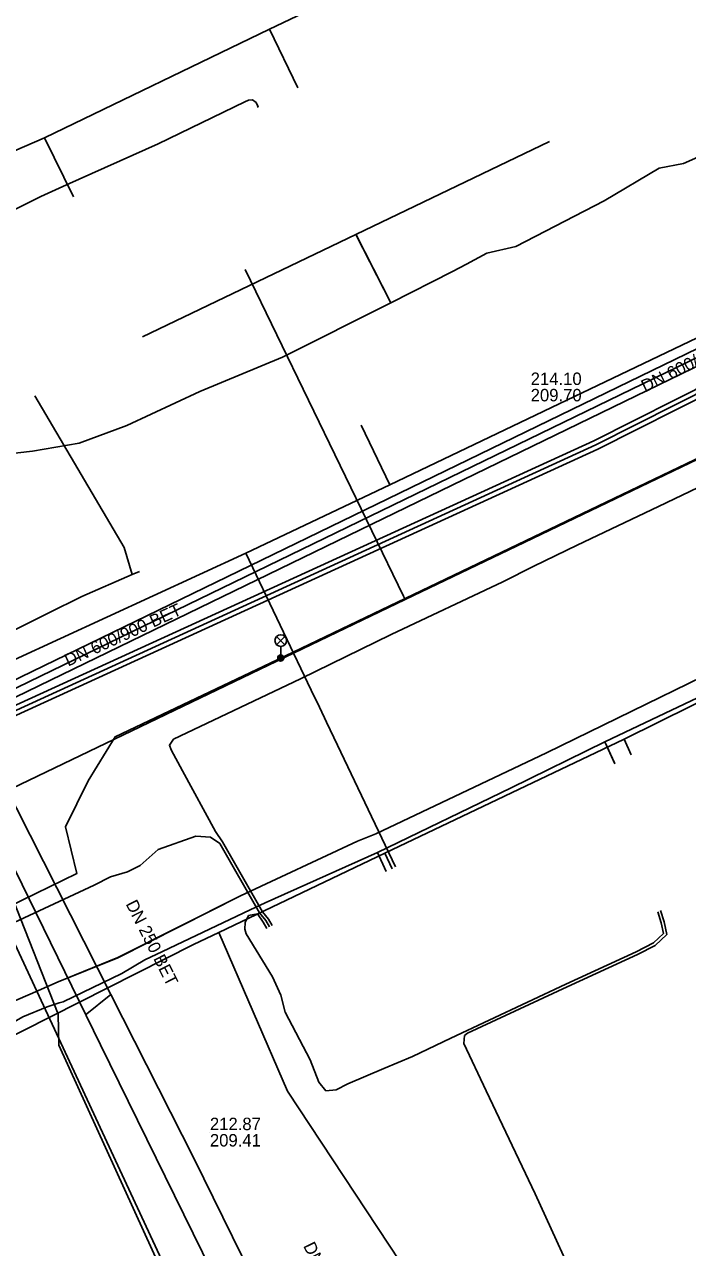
# Model space of a CAD drawing. Extents: x -595540 to -593988, y -1160850 to -1159202.
# Drawn here: x -595447.6 to -595405, y -1159984.1 to -1159905.6 of the extents above; entities that cross this region are included whole.
import ezdxf

# ---------------------------------------------------------------- set-up
doc = ezdxf.new("R2010")
doc.units = 0
for name, color, linetype in [('BVK-JEDNOTNA_popisy', 7, 'Continuous'), ('BVK-JEDNOTNA_trasa sítě', 7, 'Continuous'), ('BVK-JEDNOTNA_trasa sítě obvodem', 7, 'Continuous'), ('BVK-VODOVOD_trasa sítě', 7, 'Continuous'), ('CETIN_kabel podzemní', 7, 'Continuous'), ('CETIN_kabelovod', 7, 'Continuous'), ('DESTOVA_trasa neprovozované sítě', 7, 'Continuous'), ('DSP-SDEL-VODAFONE_kabel', 7, 'Continuous'), ('EON-NN_kabel', 7, 'Continuous'), ('EON-NN_kabel zrušené sítě', 7, 'Continuous'), ('EON-SDEL_kabel', 7, 'Continuous'), ('INNOGY-NTL_trasa sítě', 7, 'Continuous'), ('INNOGY-STL_trasa sítě', 7, 'Continuous'), ('QUANTCOM_kabel', 7, 'Continuous'), ('TSB_kabel VO', 7, 'Continuous'), ('TSB_lampy VO', 7, 'Continuous')]:
    doc.layers.add(name, color=color, linetype=linetype)

msp = doc.modelspace()

# ---------------------------------------------------------------- linework, layer by layer
at = {"layer": 'BVK-JEDNOTNA_popisy'}
for p, q in [((-595415.078, -1159928.872), (-595415.078, -1159928.872)), ((-595435.658, -1159976.709), (-595435.658, -1159976.709))]:
    msp.add_line(p, q, dxfattribs=at)
at = {"layer": 'BVK-JEDNOTNA_trasa sítě'}
for p, q in [((-595373.317, -1159913.594), (-595410.896, -1159932.598)), ((-595410.896, -1159932.598), (-595450.666, -1159950.799)), ((-595423.214, -1160005.707), (-595436.668, -1159978.426))]:
    msp.add_line(p, q, dxfattribs=at)
msp.add_lwpolyline([(-595436.668, -1159978.426), (-595442.021, -1159967.873), (-595450.666, -1159950.799)], dxfattribs=at)
at = {"layer": 'BVK-JEDNOTNA_trasa sítě obvodem'}
for p, q in [((-595411.031, -1159932.33), (-595373.452, -1159913.326)), ((-595373.182, -1159913.862), (-595410.761, -1159932.866)), ((-595450.791, -1159950.526), (-595411.021, -1159932.325)), ((-595410.771, -1159932.871), (-595450.541, -1159951.072))]:
    msp.add_line(p, q, dxfattribs=at)
at = {"layer": 'BVK-VODOVOD_trasa sítě'}
for points in [[(-595374.704, -1159919.267), (-595375.214, -1159919.512), (-595415.987, -1159939.088), (-595423.124, -1159942.515), (-595450.033, -1159955.434)], [(-595423.124, -1159942.515), (-595423.229, -1159942.297), (-595433.388, -1159921.334)], [(-595449.912, -1159956.327), (-595449.568, -1159957.045), (-595442.672, -1159971.097), (-595426.629, -1160003.791), (-595426.262, -1160004.538)]]:
    msp.add_lwpolyline(points, dxfattribs=at)
at = {"layer": 'CETIN_kabel podzemní'}
for points in [[(-595539.58, -1159992.625), (-595456.78, -1159952.4), (-595371.39, -1159910.95), (-595397.99, -1159856.09)], [(-595431.84, -1159905.91), (-595417.26, -1159898.95)], [(-595384.48, -1159904.94), (-595387.33, -1159906.22), (-595389.03, -1159907.36), (-595390.14, -1159908.48), (-595391.65, -1159910.23), (-595392.29, -1159910.87), (-595393.89, -1159911.68), (-595399.16, -1159914.34), (-595401.97, -1159915.72), (-595402.43, -1159915.85), (-595402.7, -1159915.68), (-595403.68, -1159914.15), (-595403.97, -1159913.96), (-595405.27, -1159914.52), (-595406.83, -1159914.82), (-595410.37, -1159916.92), (-595416.03, -1159919.85), (-595417.89, -1159920.28), (-595419.19, -1159921), (-595420.09, -1159921.45), (-595424.06, -1159923.47)], [(-595446.26, -1159912.89), (-595431.84, -1159905.91)], [(-595431.84, -1159905.91), (-595430.01, -1159909.68)], [(-595459.45, -1159910.18), (-595456.1, -1159917.14), (-595446.26, -1159912.89)], [(-595446.26, -1159912.89), (-595444.4, -1159916.66)], [(-595426.29, -1159919.08), (-595413.88, -1159913.12)], [(-595426.29, -1159919.08), (-595439.99, -1159925.66)], [(-595424.06, -1159923.47), (-595426.29, -1159919.08)], [(-595424.06, -1159923.47), (-595431.01, -1159926.97), (-595436.31, -1159929.17), (-595440.98, -1159931.34), (-595444.04, -1159932.48), (-595447.05, -1159933), (-595449.89, -1159933.31), (-595450.61, -1159933.59)], [(-595410.33, -1159951.65), (-595401.35, -1159947.39), (-595395.93, -1159944.76)], [(-595409.09, -1159951.49), (-595395.99, -1159944.99)], [(-595424.44, -1159958.81), (-595409.09, -1159951.49)], [(-595409.09, -1159951.49), (-595408.62, -1159952.49)], [(-595424.91, -1159958.75), (-595416.33, -1159954.6), (-595410.33, -1159951.65)], [(-595410.33, -1159951.65), (-595409.69, -1159953)], [(-595438.7, -1159965.12), (-595433.07, -1159962.44), (-595432.12, -1159962), (-595424.91, -1159958.75)], [(-595435.09, -1159963.89), (-595424.44, -1159958.81)], [(-595424.91, -1159958.75), (-595424.34, -1159959.98)], [(-595424.44, -1159958.81), (-595423.97, -1159959.8)], [(-595436.71, -1159964.66), (-595435.09, -1159963.89)], [(-595435.09, -1159963.89), (-595430.67, -1159974.08), (-595417.68, -1159993.79), (-595411.71, -1159990.96), (-595410.95, -1159992.57), (-595409.27, -1159996.12), (-595406.792, -1159999.807)], [(-595459.75, -1159976.14), (-595453.17, -1159972.99), (-595436.71, -1159964.66)], [(-595460.4, -1159976.08), (-595453.22, -1159972.52), (-595447.65, -1159969.31), (-595446.09, -1159968.67), (-595445.33, -1159968.41), (-595445.08, -1159968.35), (-595441.31, -1159966.53), (-595439.83, -1159965.66), (-595438.7, -1159965.12)]]:
    msp.add_lwpolyline(points, dxfattribs=at)
at = {"layer": 'CETIN_kabelovod'}
for points in [[(-595373.4, -1159911.37), (-595455.19, -1159951.08)], [(-595372.97, -1159912.27), (-595454.76, -1159951.99)]]:
    msp.add_lwpolyline(points, dxfattribs=at)
at = {"layer": 'DESTOVA_trasa neprovozované sítě'}
msp.add_line((-595443.66, -1159969.2), (-595442.021, -1159967.873), dxfattribs=at)
at = {"layer": 'DSP-SDEL-VODAFONE_kabel'}
for points in [[(-595467.4, -1159905.06), (-595466.64, -1159906.67), (-595466.23, -1159907.64), (-595463.85, -1159912.58), (-595463.25, -1159913.8), (-595459.54, -1159921.22), (-595456.44, -1159927.74), (-595456.16, -1159928.54), (-595455.24, -1159930.24), (-595453.23, -1159934.47), (-595452.7, -1159934.26), (-595451.82, -1159933.98), (-595451.15, -1159933.8), (-595450.608, -1159933.589), (-595449.89, -1159933.31), (-595447.05, -1159933), (-595444.04, -1159932.48), (-595440.98, -1159931.34), (-595436.31, -1159929.17), (-595431.01, -1159926.97), (-595424.06, -1159923.47)], [(-595424.06, -1159923.47), (-595420.09, -1159921.45), (-595419.19, -1159921), (-595417.89, -1159920.28), (-595416.03, -1159919.85), (-595410.37, -1159916.92), (-595406.83, -1159914.82), (-595405.27, -1159914.52), (-595403.97, -1159913.96), (-595403.68, -1159914.15), (-595402.7, -1159915.68), (-595402.43, -1159915.85), (-595401.97, -1159915.72), (-595399.16, -1159914.34), (-595393.89, -1159911.68)], [(-595424.06, -1159923.47), (-595426.273, -1159919.113)], [(-595382.9, -1159931.31), (-595383.54, -1159931.62), (-595392.92, -1159936.14), (-595393.26, -1159936.82), (-595393.43, -1159937.76), (-595393.63, -1159942.73), (-595393.7, -1159943.32), (-595394.06, -1159943.69), (-595394.93, -1159944.27), (-595395.93, -1159944.76), (-595401.35, -1159947.39), (-595410.33, -1159951.65)], [(-595410.33, -1159951.65), (-595416.33, -1159954.6), (-595424.91, -1159958.75), (-595432.12, -1159962), (-595433.07, -1159962.44), (-595438.696, -1159965.12), (-595439.83, -1159965.66), (-595441.31, -1159966.53), (-595445.08, -1159968.35), (-595445.33, -1159968.41), (-595446.09, -1159968.67), (-595447.65, -1159969.31), (-595453.22, -1159972.52), (-595460.4, -1159976.08), (-595467.41, -1159979.05), (-595468.6, -1159979.68), (-595470.64, -1159980.67), (-595474.74, -1159982.73)], [(-595410.33, -1159951.65), (-595409.668, -1159953.058)]]:
    msp.add_lwpolyline(points, dxfattribs=at)
at = {"layer": 'EON-NN_kabel'}
for points in [[(-595431.666, -1159963.441), (-595431.9, -1159963.031), (-595432.282, -1159962.567), (-595434.853, -1159958.08), (-595435.3, -1159957.41), (-595437.42, -1159953.51), (-595438.15, -1159952.16), (-595438.26, -1159951.86), (-595437.99, -1159951.48), (-595429.84, -1159947.6), (-595424.03, -1159944.77), (-595416.86, -1159941.38), (-595414.87, -1159940.37), (-595412.09, -1159939.04), (-595406.88, -1159936.55), (-595401.29, -1159933.87)], [(-595431.84, -1159963.54), (-595432.074, -1159963.13), (-595432.471, -1159962.639), (-595435.027, -1159958.18), (-595435.61, -1159957.78), (-595436.56, -1159957.71), (-595438.98, -1159958.57), (-595440.14, -1159959.6), (-595440.95, -1159960), (-595442.04, -1159960.33), (-595443.09, -1159960.86), (-595453.64, -1159965.78), (-595455.63, -1159966.8), (-595457.79, -1159967.74), (-595462.39, -1159969.77), (-595463.93, -1159970.92), (-595469.24, -1159973.4), (-595479.08, -1159978.13), (-595479.43, -1159978.899), (-595478.027, -1159980.281), (-595476.001, -1159984.615)], [(-595406.926, -1159962.569), (-595406.712, -1159963.271), (-595406.556, -1159963.953), (-595407.203, -1159964.562), (-595408.313, -1159965.127), (-595412.828, -1159967.204), (-595420.21, -1159970.67), (-595422.67, -1159971.86), (-595424.495, -1159972.632), (-595426.81, -1159973.61), (-595427.55, -1159974), (-595428.21, -1159974.05), (-595428.67, -1159973.51), (-595429.23, -1159972.06), (-595430.83, -1159969.01), (-595431.11, -1159967.91), (-595431.65, -1159966.75), (-595433.34, -1159963.99), (-595433.41, -1159963.69), (-595433.39, -1159963.26), (-595433.18, -1159962.81), (-595432.6, -1159962.69), (-595432.247, -1159963.229), (-595432.014, -1159963.639)], [(-595411.6, -1159987.64), (-595414.79, -1159980.67), (-595417.93, -1159974.05), (-595419.36, -1159971.02), (-595419.32, -1159970.51), (-595419.129, -1159970.356), (-595412.744, -1159967.386), (-595408.226, -1159965.307), (-595407.087, -1159964.727), (-595406.335, -1159964.021), (-595406.519, -1159963.219), (-595406.745, -1159962.479)]]:
    msp.add_lwpolyline(points, dxfattribs=at)
at = {"layer": 'EON-NN_kabel zrušené sítě'}
msp.add_lwpolyline([(-595432.617, -1159910.914), (-595432.563, -1159910.888), (-595432.698, -1159910.611), (-595432.917, -1159910.445), (-595433.182, -1159910.463), (-595433.423, -1159910.563), (-595438.984, -1159913.257), (-595444.856, -1159915.889), (-595446.498, -1159916.641), (-595451.757, -1159919.28), (-595454.431, -1159920.615), (-595458.33, -1159922.488), (-595458.524, -1159922.577), (-595460.025, -1159923.262), (-595465.359, -1159925.857), (-595466.817, -1159926.626), (-595466.893, -1159926.666), (-595470.726, -1159928.658), (-595473.911, -1159930.034), (-595474.215, -1159930.172), (-595474.23, -1159930.197), (-595474.305, -1159930.32), (-595474.3, -1159930.535), (-595474.067, -1159930.899)], dxfattribs=at)
at = {"layer": 'EON-SDEL_kabel'}
for points in [[(-595441.56, -1159965.511), (-595433.7, -1159961.551), (-595426.19, -1159958.041), (-595425.02, -1159957.561), (-595414.07, -1159952.361), (-595398.55, -1159944.791)], [(-595490.33, -1159988.411), (-595477.63, -1159982.541), (-595476.4, -1159981.991), (-595466.6, -1159976.821), (-595451.16, -1159969.721), (-595450.19, -1159969.131), (-595447.2, -1159967.861), (-595445.4, -1159967.071), (-595441.56, -1159965.511)]]:
    msp.add_lwpolyline(points, dxfattribs=at)
at = {"layer": 'INNOGY-NTL_trasa sítě'}
for points in [[(-595448.22, -1159946.4), (-595433.362, -1159939.551), (-595424.12, -1159935.15), (-595404.39, -1159925.71), (-595398.46, -1159922.89), (-595379.56, -1159913.5)], [(-595424.12, -1159935.15), (-595425.95, -1159931.33)], [(-595433.362, -1159939.551), (-595428.946, -1159948.785)], [(-595428.946, -1159948.785), (-595428.807, -1159949.075), (-595428.312, -1159950.111), (-595428.174, -1159950.4)], [(-595428.174, -1159950.4), (-595427.471, -1159951.875), (-595423.752, -1159959.681)], [(-595459.42, -1159952.03), (-595450.02, -1159960.712), (-595429.637, -1160004.55)]]:
    msp.add_lwpolyline(points, dxfattribs=at)
at = {"layer": 'INNOGY-STL_trasa sítě'}
for points in [[(-595440.64, -1159940.92), (-595441.16, -1159939.18), (-595446.89, -1159929.44)], [(-595440.17, -1159940.72), (-595440.64, -1159940.92), (-595443.87, -1159942.33), (-595446.04, -1159943.4), (-595458.62, -1159949.64), (-595514.88, -1159976.66), (-595522.77, -1159980.24), (-595525.84, -1159981.9), (-595526.42, -1159982.16)]]:
    msp.add_lwpolyline(points, dxfattribs=at)
at = {"layer": 'QUANTCOM_kabel'}
msp.add_lwpolyline([(-595490.33, -1159988.41), (-595477.63, -1159982.54), (-595476.4, -1159981.99), (-595466.6, -1159976.82), (-595451.16, -1159969.72), (-595450.19, -1159969.13), (-595447.2, -1159967.86), (-595445.4, -1159967.07), (-595441.56, -1159965.51), (-595433.7, -1159961.55), (-595426.19, -1159958.04), (-595425.02, -1159957.56), (-595414.07, -1159952.36), (-595398.55, -1159944.79)], dxfattribs=at)
at = {"layer": 'TSB_kabel VO'}
for points in [[(-595454.11, -1159961.8), (-595454.68, -1159958.17), (-595452.6, -1159958.78), (-595449.69, -1159960.49), (-595448.58, -1159962.24), (-595444.2, -1159960.11), (-595444.92, -1159957.12), (-595443.46, -1159954.16), (-595441.74, -1159951.34), (-595431.34, -1159946.39), (-595402.52, -1159932.56), (-595386.06, -1159924.89), (-595383.43, -1159923.74), (-595379.16, -1159922.75), (-595374.72, -1159923.58), (-595372.35, -1159925.47), (-595371.45, -1159926.68), (-595376.5, -1159929.79)], [(-595454.11, -1159961.8), (-595456.04, -1159957.89), (-595455.41, -1159957.66), (-595449.28, -1159959.9), (-595448.33, -1159961.7), (-595445.4, -1159969.13), (-595445.34, -1159971.12), (-595438.7, -1159985.73), (-595435.7, -1159992.2), (-595436.24, -1159997.2), (-595436.25, -1160002), (-595435.21, -1160007.7), (-595434.29, -1160011.13), (-595434.5, -1160011.94)]]:
    msp.add_lwpolyline(points, dxfattribs=at)
at = {"layer": 'TSB_lampy VO'}
for p, q in [((-595431.375, -1159945.42), (-595430.845, -1159944.89)), ((-595431.375, -1159944.89), (-595430.845, -1159945.42)), ((-595431.375, -1159945.42), (-595430.845, -1159944.89)), ((-595431.375, -1159944.89), (-595430.845, -1159945.42)), ((-595431.11, -1159945.53), (-595431.11, -1159946.28)), ((-595431.11, -1159945.53), (-595431.11, -1159946.28))]:
    msp.add_line(p, q, dxfattribs=at)
for centre, radius in [((-595431.11, -1159945.155), 0.375), ((-595431.11, -1159945.155), 0.375), ((-595431.11, -1159946.28), 0.2), ((-595431.11, -1159946.28), 0.2), ((-595431.11, -1159946.28), 0.145), ((-595431.11, -1159946.28), 0.145), ((-595431.11, -1159946.28), 0.0876), ((-595431.11, -1159946.28), 0.0876)]:
    msp.add_circle(centre, radius, dxfattribs=at)

# ---------------------------------------------------------------- texts
at = {"layer": 'BVK-JEDNOTNA_popisy'}
for s, rotation, p in [('DN 600/900 BET', 26.3357, (-595407.738, -1159929.233)), ('DN 600/900 BET', 24.62083, (-595444.754, -1159946.831)), ('DN 250 BET', 296.79214, (-595441.08, -1159962.057)), ('DN 250 BEO', 296.28169, (-595429.687, -1159984.009))]:
    msp.add_text(s, height=0.8, rotation=rotation, dxfattribs=at).set_placement(p)
for s, p in [('214.10', (-595415.078, -1159928.747)), ('209.70', (-595415.078, -1159929.797)), ('212.87', (-595435.658, -1159976.584)), ('209.41', (-595435.658, -1159977.634))]:
    msp.add_text(s, height=0.8, dxfattribs=at).set_placement(p)

doc.saveas('drawing.dxf')
